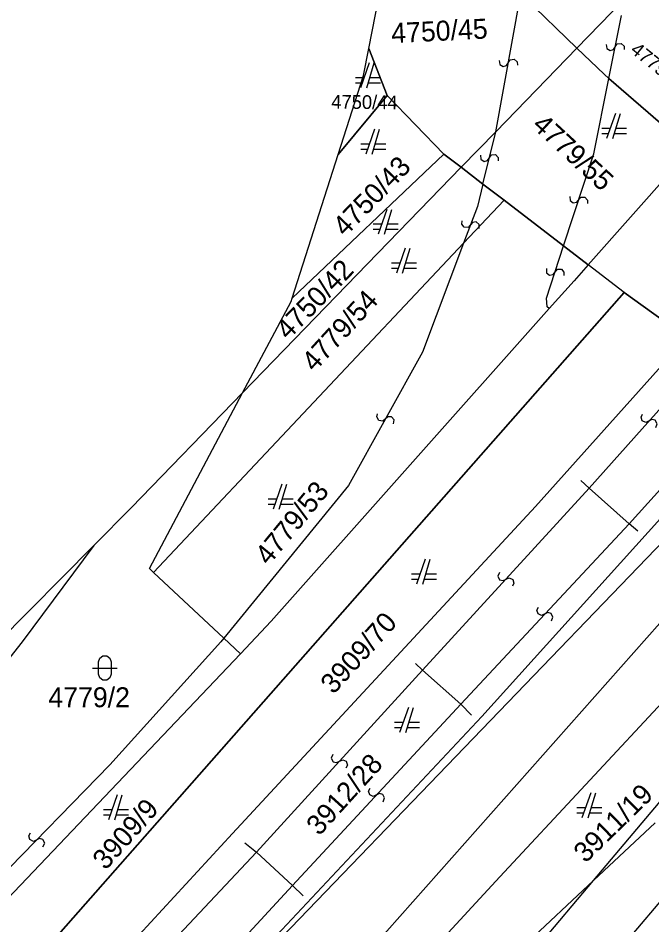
# Model space of a CAD drawing. Extents: x -266179 to -264727, y -1243225 to -1241702.
# Drawn here: x -264950.9 to -264900.1, y -1242603 to -1242530.3 of the extents above; entities that cross this region are included whole.
import ezdxf

# ---------------------------------------------------------------- set-up
doc = ezdxf.new("R2010")
doc.units = 0
for name, color, linetype in [('Vrstva 1', 7, 'Continuous'), ('Vrstva 19', 7, 'Continuous'), ('Vrstva 2', 7, 'Continuous'), ('Vrstva 21', 7, 'Continuous')]:
    doc.layers.add(name, color=color, linetype=linetype)

msp = doc.modelspace()

# ---------------------------------------------------------------- linework, layer by layer
at = {"layer": 'Vrstva 1'}
for p, q in [((-264922.76, -1242532.73), (-264920.13, -1242519.13)), ((-264906.09, -1242532.68), (-264910.58, -1242528.34)), ((-264910.58, -1242528.34), (-264906.09, -1242532.68)), ((-264906.09, -1242532.68), (-264902.39, -1242528.86)), ((-264923.18, -1242534.88), (-264922.76, -1242532.73)), ((-264921.28, -1242536.49), (-264922.76, -1242532.73)), ((-264922.76, -1242532.73), (-264921.28, -1242536.49)), ((-264912.59, -1242539.39), (-264906.09, -1242532.68)), ((-264903.91, -1242534.78), (-264906.09, -1242532.68)), ((-264906.09, -1242532.68), (-264903.91, -1242534.78)), ((-264922.72, -1242533.86), (-264923.42, -1242535.86)), ((-264922.92, -1242535.86), (-264922.32, -1242533.86)), ((-264925.21, -1242541.22), (-264923.18, -1242534.88)), ((-264923.14, -1242535.06), (-264923.82, -1242535.06)), ((-264921.82, -1242535.06), (-264922.68, -1242535.06)), ((-264903.52, -1242535.12), (-264903.91, -1242534.78)), ((-264903.91, -1242534.78), (-264903.52, -1242535.12)), ((-264896.97, -1242540.8), (-264903.52, -1242535.12)), ((-264903.52, -1242535.12), (-264896.97, -1242540.8)), ((-264923.82, -1242535.46), (-264923.28, -1242535.46)), ((-264922.8, -1242535.46), (-264921.82, -1242535.46)), ((-264921.28, -1242536.49), (-264925.21, -1242541.22)), ((-264925.21, -1242541.22), (-264921.28, -1242536.49)), ((-264916.75, -1242541.18), (-264921.28, -1242536.49)), ((-264921.28, -1242536.49), (-264916.75, -1242541.18)), ((-264903, -1242537.94), (-264903.7, -1242539.94)), ((-264903.2, -1242539.94), (-264902.6, -1242537.94)), ((-264922.29, -1242539.18), (-264922.99, -1242541.18)), ((-264922.49, -1242541.18), (-264921.89, -1242539.18)), ((-264915.36, -1242542.24), (-264912.59, -1242539.39)), ((-264903.42, -1242539.14), (-264904.1, -1242539.14)), ((-264904.1, -1242539.54), (-264903.56, -1242539.54)), ((-264903.08, -1242539.54), (-264902.1, -1242539.54)), ((-264902.1, -1242539.14), (-264902.96, -1242539.14)), ((-264922.71, -1242540.38), (-264923.39, -1242540.38)), ((-264923.39, -1242540.78), (-264922.85, -1242540.78)), ((-264922.37, -1242540.78), (-264921.39, -1242540.78)), ((-264921.39, -1242540.38), (-264922.25, -1242540.38)), ((-264896.97, -1242540.8), (-264905.18, -1242550.06)), ((-264916.75, -1242541.18), (-264928.9, -1242552.74)), ((-264928.9, -1242552.74), (-264916.75, -1242541.18)), ((-264928.9, -1242552.74), (-264925.21, -1242541.22)), ((-264915.36, -1242542.24), (-264916.75, -1242541.18)), ((-264916.75, -1242541.18), (-264915.36, -1242542.24)), ((-264932.87, -1242560.32), (-264915.36, -1242542.24)), ((-264913.61, -1242543.58), (-264915.36, -1242542.24)), ((-264915.36, -1242542.24), (-264913.61, -1242543.58)), ((-264911.92, -1242544.87), (-264913.61, -1242543.58)), ((-264913.61, -1242543.58), (-264911.92, -1242544.87)), ((-264911.92, -1242544.87), (-264915.16, -1242548.31)), ((-264915.16, -1242548.31), (-264911.92, -1242544.87)), ((-264907.15, -1242548.54), (-264911.92, -1242544.87)), ((-264911.92, -1242544.87), (-264907.15, -1242548.54)), ((-264921.31, -1242545.61), (-264922.01, -1242547.61)), ((-264921.51, -1242547.61), (-264920.91, -1242545.61)), ((-264921.73, -1242546.81), (-264922.41, -1242546.81)), ((-264920.41, -1242546.81), (-264921.27, -1242546.81)), ((-264922.41, -1242547.21), (-264921.87, -1242547.21)), ((-264921.39, -1242547.21), (-264920.41, -1242547.21)), ((-264915.16, -1242548.31), (-264940.01, -1242574.71)), ((-264940.01, -1242574.71), (-264915.16, -1242548.31)), ((-264919.85, -1242548.73), (-264920.55, -1242550.73)), ((-264920.05, -1242550.73), (-264919.45, -1242548.73)), ((-264905.18, -1242550.06), (-264907.15, -1242548.54)), ((-264907.15, -1242548.54), (-264905.18, -1242550.06)), ((-264920.27, -1242549.93), (-264920.95, -1242549.93)), ((-264920.95, -1242550.33), (-264920.41, -1242550.33)), ((-264919.93, -1242550.33), (-264918.95, -1242550.33)), ((-264918.95, -1242549.93), (-264919.81, -1242549.93)), ((-264905.18, -1242550.06), (-264906.31, -1242551.34)), ((-264902.3, -1242552.28), (-264905.18, -1242550.06)), ((-264906.31, -1242551.34), (-264908.3, -1242553.57)), ((-264957.36, -1242614.78), (-264902.3, -1242552.28)), ((-264902.3, -1242552.28), (-264957.36, -1242614.78)), ((-264897.29, -1242555.89), (-264902.3, -1242552.28)), ((-264902.3, -1242552.28), (-264897.29, -1242555.89)), ((-264932.87, -1242560.32), (-264928.98, -1242552.99)), ((-264928.98, -1242552.99), (-264928.9, -1242552.74)), ((-264908.3, -1242553.57), (-264930.57, -1242578.63)), ((-264909.4, -1242569.43), (-264897.29, -1242555.89)), ((-264941.78, -1242569.52), (-264932.87, -1242560.32)), ((-264940.34, -1242574.41), (-264932.87, -1242560.32)), ((-264890.64, -1242560.67), (-264913.7, -1242586.25)), ((-264950.43, -1242625.46), (-264889.07, -1242561.69)), ((-264946.23, -1242631.57), (-264886.04, -1242563.65)), ((-264929.73, -1242567.65), (-264930.43, -1242569.65)), ((-264929.93, -1242569.65), (-264929.33, -1242567.65)), ((-264930.15, -1242568.85), (-264930.83, -1242568.85)), ((-264930.83, -1242569.25), (-264930.29, -1242569.25)), ((-264929.81, -1242569.25), (-264928.83, -1242569.25)), ((-264928.83, -1242568.85), (-264929.69, -1242568.85)), ((-264944.78, -1242572.55), (-264941.78, -1242569.52)), ((-264933.68, -1242595.65), (-264909.4, -1242569.43)), ((-264963.38, -1242591.33), (-264944.78, -1242572.55)), ((-264944.78, -1242572.55), (-264950.53, -1242580.29)), ((-264918.24, -1242573.66), (-264918.94, -1242575.66)), ((-264918.44, -1242575.66), (-264917.84, -1242573.66)), ((-264904.75, -1242599.4), (-264882.99, -1242573.53)), ((-264940.01, -1242574.71), (-264940.34, -1242574.41)), ((-264934.38, -1242579.99), (-264940.01, -1242574.71)), ((-264918.66, -1242574.86), (-264919.34, -1242574.86)), ((-264917.34, -1242574.86), (-264918.2, -1242574.86)), ((-264919.34, -1242575.26), (-264918.8, -1242575.26)), ((-264918.32, -1242575.26), (-264917.34, -1242575.26)), ((-264930.57, -1242578.63), (-264933.05, -1242581.23)), ((-264950.53, -1242580.29), (-264962.16, -1242594.83)), ((-264933.05, -1242581.23), (-264934.38, -1242579.99)), ((-264933.05, -1242581.23), (-264951.72, -1242600.87)), ((-264885.72, -1242585), (-264932.84, -1242640.32)), ((-264919.59, -1242585.55), (-264920.29, -1242587.55)), ((-264919.79, -1242587.55), (-264919.19, -1242585.55)), ((-264913.7, -1242586.25), (-264931.79, -1242605.55)), ((-264920.01, -1242586.75), (-264920.69, -1242586.75)), ((-264918.69, -1242586.75), (-264919.55, -1242586.75)), ((-264920.69, -1242587.15), (-264920.15, -1242587.15)), ((-264919.67, -1242587.15), (-264918.69, -1242587.15)), ((-264942.92, -1242592.54), (-264943.62, -1242594.54)), ((-264943.12, -1242594.54), (-264942.52, -1242592.54)), ((-264904.98, -1242592.39), (-264905.68, -1242594.39)), ((-264905.18, -1242594.39), (-264904.58, -1242592.39)), ((-264943.34, -1242593.74), (-264944.02, -1242593.74)), ((-264942.02, -1242593.74), (-264942.88, -1242593.74)), ((-264905.4, -1242593.59), (-264906.08, -1242593.59)), ((-264906.08, -1242593.99), (-264905.54, -1242593.99)), ((-264905.06, -1242593.99), (-264904.08, -1242593.99)), ((-264904.08, -1242593.59), (-264904.94, -1242593.59)), ((-264944.02, -1242594.14), (-264943.48, -1242594.14)), ((-264943, -1242594.14), (-264942.02, -1242594.14)), ((-264941.17, -1242603.77), (-264933.68, -1242595.65)), ((-264939.76, -1242641), (-264904.75, -1242599.4))]:
    msp.add_line(p, q, dxfattribs=at)
msp.add_lwpolyline([(-264944.41, -1242581.88), (-264944.31, -1242581.59), (-264944.06, -1242581.41), (-264943.75, -1242581.41), (-264943.5, -1242581.59), (-264943.4, -1242581.88), (-264943.4, -1242582.88), (-264943.5, -1242583.17), (-264943.75, -1242583.35), (-264944.06, -1242583.35), (-264944.31, -1242583.17), (-264944.41, -1242582.88)], close=True, dxfattribs=at)
msp.add_lwpolyline([(-264944.91, -1242582.38), (-264943.64, -1242582.38), (-264942.91, -1242582.38)], dxfattribs=at)
at = {"layer": 'Vrstva 19'}
msp.add_line((-264885.72, -1242585), (-264932.84, -1242640.32), dxfattribs=at)
at = {"layer": 'Vrstva 2'}
for p, q in [((-264912.59, -1242539.39), (-264910.58, -1242528.34)), ((-264903.52, -1242535.12), (-264902.5, -1242530.07)), ((-264904.74, -1242541.16), (-264903.52, -1242535.12)), ((-264913.61, -1242543.58), (-264912.59, -1242539.39)), ((-264907.15, -1242548.54), (-264904.74, -1242541.16)), ((-264913.61, -1242543.58), (-264914.05, -1242545.38)), ((-264914.05, -1242545.38), (-264915.16, -1242548.31)), ((-264915.16, -1242548.31), (-264918.46, -1242557.05)), ((-264908.52, -1242552.74), (-264907.15, -1242548.54)), ((-264908.47, -1242553.43), (-264908.52, -1242552.74)), ((-264908.3, -1242553.57), (-264908.47, -1242553.43)), ((-264918.46, -1242557.05), (-264924.38, -1242567.75)), ((-264895.51, -1242557.17), (-264905.09, -1242567.97)), ((-264891.92, -1242559.75), (-264901.9, -1242570.81)), ((-264924.38, -1242567.75), (-264934.38, -1242579.99)), ((-264905.78, -1242567.35), (-264905.09, -1242567.97)), ((-264918.46, -1242582.56), (-264905.09, -1242567.97)), ((-264905.09, -1242567.97), (-264901.9, -1242570.81)), ((-264901.9, -1242570.81), (-264915.39, -1242585.28)), ((-264901.19, -1242571.4), (-264901.9, -1242570.81)), ((-264934.62, -1242580.28), (-264943.51, -1242590.15)), ((-264934.38, -1242579.99), (-264934.62, -1242580.28)), ((-264919.02, -1242582.01), (-264918.46, -1242582.56)), ((-264931.77, -1242597.14), (-264918.46, -1242582.56)), ((-264918.46, -1242582.56), (-264915.39, -1242585.28)), ((-264898.52, -1242584.36), (-264912.25, -1242599.12)), ((-264915.39, -1242585.28), (-264928.88, -1242599.81)), ((-264915.39, -1242585.28), (-264914.53, -1242586.16)), ((-264943.51, -1242590.15), (-264955.23, -1242602.16)), ((-264904.75, -1242599.4), (-264899.81, -1242594.78)), ((-264932.68, -1242596.39), (-264931.77, -1242597.14)), ((-264945.5, -1242611.73), (-264931.77, -1242597.14)), ((-264931.77, -1242597.14), (-264928.88, -1242599.81)), ((-264912.25, -1242599.12), (-264930.53, -1242618.87)), ((-264928.88, -1242599.81), (-264942.56, -1242614.63)), ((-264928.88, -1242599.81), (-264928.03, -1242600.63)), ((-264904.75, -1242599.4), (-264915.43, -1242609.39))]:
    msp.add_line(p, q, dxfattribs=at)
for points in [[(-264903.735, -1242532.397), (-264903.689, -1242532.723), (-264903.417, -1242532.89), (-264903.144, -1242532.803), (-264902.849, -1242532.352), (-264902.535, -1242532.314), (-264902.302, -1242532.524), (-264902.285, -1242532.793)], [(-264912.314, -1242533.682), (-264912.261, -1242534.006), (-264911.986, -1242534.168), (-264911.715, -1242534.075), (-264911.428, -1242533.619), (-264911.115, -1242533.574), (-264910.878, -1242533.78), (-264910.856, -1242534.048)], [(-264913.817, -1242541.259), (-264913.783, -1242541.586), (-264913.518, -1242541.764), (-264913.242, -1242541.687), (-264912.929, -1242541.249), (-264912.614, -1242541.222), (-264912.39, -1242541.442), (-264912.383, -1242541.711)], [(-264906.642, -1242544.57), (-264906.634, -1242544.898), (-264906.383, -1242545.096), (-264906.102, -1242545.041), (-264905.757, -1242544.628), (-264905.44, -1242544.626), (-264905.233, -1242544.862), (-264905.248, -1242545.13)], [(-264913.921, -1242547.158), (-264913.914, -1242546.829), (-264914.156, -1242546.62), (-264914.439, -1242546.662), (-264914.804, -1242547.058), (-264915.12, -1242547.046), (-264915.315, -1242546.8), (-264915.289, -1242546.532)], [(-264908.532, -1242550.36), (-264908.524, -1242550.688), (-264908.273, -1242550.886), (-264907.992, -1242550.831), (-264907.647, -1242550.418), (-264907.33, -1242550.416), (-264907.123, -1242550.652), (-264907.138, -1242550.92)], [(-264920.788, -1242562.807), (-264920.734, -1242562.482), (-264920.943, -1242562.241), (-264921.23, -1242562.242), (-264921.647, -1242562.583), (-264921.958, -1242562.525), (-264922.117, -1242562.255), (-264922.052, -1242561.993)], [(-264899.772, -1242563.105), (-264899.649, -1242562.8), (-264899.8, -1242562.519), (-264900.08, -1242562.458), (-264900.561, -1242562.699), (-264900.852, -1242562.575), (-264900.948, -1242562.276), (-264900.828, -1242562.035)], [(-264912.294, -1242574.721), (-264912.423, -1242575.024), (-264912.276, -1242575.308), (-264911.997, -1242575.374), (-264911.511, -1242575.14), (-264911.223, -1242575.269), (-264911.132, -1242575.57), (-264911.256, -1242575.809)], [(-264908.131, -1242578.593), (-264908, -1242578.291), (-264908.144, -1242578.006), (-264908.422, -1242577.938), (-264908.91, -1242578.167), (-264909.197, -1242578.036), (-264909.286, -1242577.735), (-264909.159, -1242577.497)], [(-264925.635, -1242589.307), (-264925.763, -1242589.611), (-264925.616, -1242589.894), (-264925.337, -1242589.959), (-264924.852, -1242589.725), (-264924.563, -1242589.853), (-264924.471, -1242590.153), (-264924.595, -1242590.393)], [(-264921.619, -1242593.092), (-264921.489, -1242592.79), (-264921.634, -1242592.505), (-264921.913, -1242592.438), (-264922.399, -1242592.668), (-264922.687, -1242592.537), (-264922.776, -1242592.236), (-264922.651, -1242591.998)], [(-264948.868, -1242596.715), (-264948.73, -1242596.416), (-264948.868, -1242596.128), (-264949.145, -1242596.053), (-264949.637, -1242596.271), (-264949.922, -1242596.133), (-264950.003, -1242595.83), (-264949.872, -1242595.595)]]:
    msp.add_lwpolyline(points, dxfattribs=at)
at = {"layer": 'Vrstva 21'}
msp.add_line((-264885.72, -1242585), (-264932.84, -1242640.32), dxfattribs=at)

# ---------------------------------------------------------------- texts
at = {"layer": 'Vrstva 1'}
for s, height, rotation, p in [('4750/45', 1.6, 2.86479, (-264920.924, -1242532.293)), ('4779/56', 1.1, 321.14284, (-264901.874, -1242532.981)), ('4750/44', 1.1, 359.35913, (-264925.771, -1242537.532)), ('4779/55', 1.6, 317.18944, (-264909.756, -1242538.986)), ('4750/43', 1.6, 46.00851, (-264924.652, -1242547.867)), ('4750/42', 1.6, 46.00851, (-264929.222, -1242556.147)), ('4779/54', 1.6, 47.61279, (-264927.109, -1242558.712)), ('4779/53', 1.6, 50.53488, (-264930.779, -1242574.222)), ('3909/70', 1.6, 47.84198, (-264925.588, -1242584.547)), ('3912/28', 1.6, 47.84198, (-264926.726, -1242595.894)), ('3911/19', 1.6, 44.34693, (-264905.393, -1242598.069)), ('3909/9', 1.6, 48.35764, (-264943.846, -1242598.643))]:
    msp.add_text(s, height=height, rotation=rotation, dxfattribs=at).set_placement(p)
msp.add_text('4779/2', height=1.6, dxfattribs=at).set_placement((-264948.439, -1242585.52))

doc.saveas('drawing.dxf')
